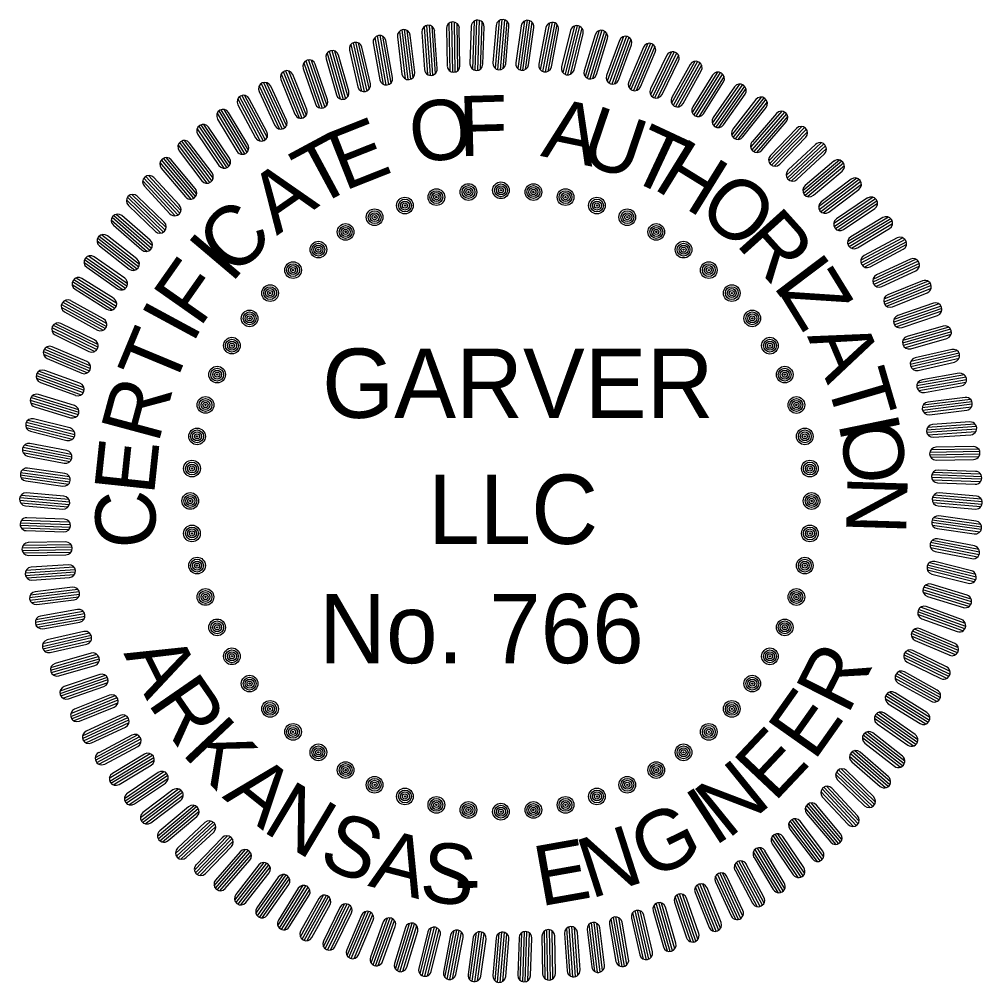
# Model space of a CAD drawing. Extents: x 1373862 to 1376999, y 1168398 to 1170455.
# Drawn here: x 1376477.4 to 1376713.7, y 1168432.6 to 1168668.8 of the extents above; entities that cross this region are included whole.
import ezdxf

# ---------------------------------------------------------------- set-up
doc = ezdxf.new("R2010")
doc.units = 0
doc.layers.add('G-ANNO-TEXT', color=7, linetype='Continuous')

# ---------------------------------------------------------------- blocks, each defined once
blk = doc.blocks.new('SEALDO')
at = {"layer": 'G-ANNO-TEXT'}
for radius in [0.0396, 0.0305, 0.0213, 0.0122, 0.00305]:
    blk.add_circle((1.403, -0.4559), radius, dxfattribs=at)
blk = doc.blocks.new('SEALRI')
at = {"layer": 'G-ANNO-TEXT'}
for p, q in [((-0.0226, 2.2583), (-0.0381, 2.0809)), ((-0.0083, 2.2815), (-0.0281, 2.0555)), ((0.0043, 2.2859), (-0.0164, 2.049)), ((0.0164, 2.2848), (-0.0043, 2.0479)), ((0.0281, 2.2783), (0.0083, 2.0523)), ((0.0226, 2.0756), (0.0381, 2.253))]:
    blk.add_line(p, q, dxfattribs=at)
for centre, start, end in [((0.0078, 2.2556), 355, 175), ((-0.0078, 2.0782), 175, 355)]:
    blk.add_arc(centre, 0.0305, start, end, dxfattribs=at)

msp = doc.modelspace()

# ---------------------------------------------------------------- block references
at = {"layer": 'G-ANNO-TEXT'}
for name, xscale, yscale, rotation in [('SEALRI', 51.64309671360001, 51.643096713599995, 3.0000000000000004), ('SEALRI', 51.64309671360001, 51.6430967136, -2.999999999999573), ('SEALRI', 51.643096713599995, 51.643096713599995, 12), ('SEALRI', 51.64309671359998, 51.64309671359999, 9.000000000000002), ('SEALRI', 51.6430967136, 51.643096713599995, 6.000000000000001), ('SEALRI', 51.6430967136, 51.643096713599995, -5.99999999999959), ('SEALRI', 51.643096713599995, 51.64309671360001, -8.999999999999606), ('SEALRI', 51.64309671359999, 51.64309671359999, -11.999999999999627), ('SEALRI', 51.643096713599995, 51.64309671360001, 15.000000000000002), ('SEALRI', 51.6430967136, 51.64309671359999, -14.99999999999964), ('SEALRI', 51.6430967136, 51.643096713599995, 20.99999999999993), ('SEALRI', 51.64309671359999, 51.64309671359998, 18.000000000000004), ('SEALRI', 51.643096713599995, 51.643096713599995, -17.999999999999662), ('SEALRI', 51.64309671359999, 51.64309671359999, -20.999999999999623), ('SEALRI', 51.6430967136, 51.643096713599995, 23.99999999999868), ('SEALRI', 51.643096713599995, 51.6430967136, -23.999999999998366), ('SEALRI', 51.6430967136, 51.643096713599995, 26.999999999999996), ('SEALRI', 51.643096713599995, 51.643096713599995, -26.99999999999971), ('SEALRI', 51.6430967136, 51.64309671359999, 30.000000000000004), ('SEALRI', 51.64309671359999, 51.6430967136, -29.999999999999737), ('SEALRI', 51.643096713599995, 51.64309671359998, 33), ('SEALRI', 51.6430967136, 51.6430967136, -32.999999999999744), ('SEALRI', 51.643096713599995, 51.64309671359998, 36), ('SEALRI', 51.643096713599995, 51.643096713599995, -35.999999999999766), ('SEALRI', 51.6430967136, 51.6430967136, 38.999999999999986), ('SEALRI', 51.64309671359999, 51.64309671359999, -38.99999999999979), ('SEALRI', 51.64309671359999, 51.64309671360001, 41.99999999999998), ('SEALRI', 51.6430967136, 51.643096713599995, -41.99999999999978), ('SEALRI', 51.643096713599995, 51.64309671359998, 44.999999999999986), ('SEALRI', 51.6430967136, 51.6430967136, -44.99999999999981), ('SEALRI', 51.643096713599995, 51.6430967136, 48), ('SEALRI', 51.6430967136, 51.643096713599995, -47.99999999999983), ('SEALDO', 51.64309671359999, 51.64309671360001, 113.99999999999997), ('SEALDO', 51.643096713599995, 51.64309671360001, 107.99999999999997), ('SEALDO', 51.64309671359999, 51.64309671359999, 101.99999999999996), ('SEALRI', 51.643096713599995, 51.6430967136, 50.99999999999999), ('SEALDO', 51.6430967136, 51.6430967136, 125.99999999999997), ('SEALDO', 51.64309671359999, 51.64309671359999, 119.99999999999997), ('SEALDO', 51.6430967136, 51.643096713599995, 95.99999999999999), ('SEALRI', 51.643096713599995, 51.6430967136, -50.99999999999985), ('SEALDO', 51.643096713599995, 51.643096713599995, 90), ('SEALRI', 51.643096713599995, 51.64309671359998, 54.00000000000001), ('SEALDO', 51.6430967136, 51.643096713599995, 131.99999999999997), ('SEALDO', 51.6430967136, 51.6430967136, 83.99999999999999), ('SEALRI', 51.6430967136, 51.643096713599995, -53.99999999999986), ('SEALDO', 51.643096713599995, 51.643096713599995, 138), ('SEALDO', 51.643096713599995, 51.6430967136, 77.99999999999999), ('SEALRI', 51.643096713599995, 51.6430967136, 56.999999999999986), ('SEALRI', 51.6430967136, 51.6430967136, -56.999999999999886), ('SEALDO', 51.64309671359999, 51.64309671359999, 144), ('SEALDO', 51.64309671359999, 51.64309671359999, 72), ('SEALRI', 51.64309671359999, 51.6430967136, 59.999999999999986), ('SEALDO', 51.643096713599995, 51.6430967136, 150), ('SEALDO', 51.6430967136, 51.6430967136, 66.00000000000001), ('SEALRI', 51.64309671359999, 51.64309671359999, -59.99999999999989), ('SEALRI', 51.64309671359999, 51.64309671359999, 63), ('SEALRI', 51.643096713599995, 51.6430967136, -62.99999999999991), ('SEALDO', 51.643096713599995, 51.6430967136, 156.00000000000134), ('SEALDO', 51.643096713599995, 51.6430967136, 60.00000000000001), ('SEALRI', 51.6430967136, 51.6430967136, 65.99999999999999), ('SEALRI', 51.6430967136, 51.64309671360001, -65.99999999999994), ('SEALDO', 51.64309671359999, 51.6430967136, 162.00000000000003), ('SEALDO', 51.643096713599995, 51.64309671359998, 54.00000000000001), ('SEALRI', 51.64309671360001, 51.6430967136, 68.99999999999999), ('SEALRI', 51.643096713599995, 51.6430967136, -68.99999999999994), ('SEALDO', 51.64309671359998, 51.643096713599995, 168.00000000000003), ('SEALDO', 51.6430967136, 51.643096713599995, 48.00000000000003), ('SEALRI', 51.64309671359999, 51.64309671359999, 72), ('SEALRI', 51.643096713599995, 51.6430967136, -71.99999999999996), ('SEALDO', 51.6430967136, 51.643096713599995, 174.00000000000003), ('SEALDO', 51.643096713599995, 51.6430967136, 42.00000000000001), ('SEALRI', 51.643096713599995, 51.6430967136, 75.00000000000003), ('SEALRI', 51.6430967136, 51.643096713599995, -74.99999999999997), ('SEALRI', 51.643096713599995, 51.643096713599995, 78.00000000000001), ('SEALDO', 51.643096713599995, 51.643096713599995, -179.99999999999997), ('SEALDO', 51.643096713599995, 51.64309671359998, 36), ('SEALRI', 51.643096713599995, 51.643096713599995, -78), ('SEALRI', 51.643096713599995, 51.64309671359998, 81), ('SEALDO', 51.643096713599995, 51.6430967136, 29.999999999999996), ('SEALRI', 51.64309671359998, 51.64309671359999, -81.00000000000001), ('SEALDO', 51.64309671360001, 51.643096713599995, -173.99999999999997), ('SEALRI', 51.6430967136, 51.643096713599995, 84.00000000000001), ('SEALRI', 51.6430967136, 51.643096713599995, -84.00000000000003), ('SEALDO', 51.64309671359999, 51.6430967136, -167.99999999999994), ('SEALDO', 51.6430967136, 51.643096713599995, 23.99999999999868), ('SEALRI', 51.6430967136, 51.6430967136, 87.00000000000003), ('SEALRI', 51.6430967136, 51.6430967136, -87.00000000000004), ('SEALRI', 51.643096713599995, 51.643096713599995, 90.00000000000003), ('SEALDO', 51.64309671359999, 51.64309671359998, -161.9999999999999), ('SEALDO', 51.64309671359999, 51.64309671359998, 18.000000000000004), ('SEALRI', 51.643096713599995, 51.643096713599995, -90.00000000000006), ('SEALRI', 51.64309671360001, 51.643096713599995, 93), ('SEALRI', 51.64309671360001, 51.6430967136, -93.00000000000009), ('SEALDO', 51.6430967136, 51.6430967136, -156.00000000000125), ('SEALDO', 51.643096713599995, 51.643096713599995, 12), ('SEALRI', 51.6430967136, 51.6430967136, 96.00000000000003), ('SEALRI', 51.643096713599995, 51.643096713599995, -96.0000000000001), ('SEALRI', 51.643096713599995, 51.643096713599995, 99.00000000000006), ('SEALDO', 51.6430967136, 51.643096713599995, -149.99999999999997), ('SEALDO', 51.6430967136, 51.643096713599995, 6.000000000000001), ('SEALRI', 51.643096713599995, 51.643096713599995, -99.00000000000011), ('SEALRI', 51.64309671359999, 51.64309671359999, 102.00000000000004), ('SEALDO', 51.64309671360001, 51.6430967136, -143.99999999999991), ('SEALRI', 51.643096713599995, 51.6430967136, -102.00000000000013), ('SEALRI', 51.6430967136, 51.643096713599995, 105.00000000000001), ('SEALRI', 51.6430967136, 51.643096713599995, -105.00000000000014), ('SEALDO', 51.6430967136, 51.6430967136, -137.9999999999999), ('SEALDO', 51.6430967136, 51.6430967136, -6.000000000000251), ('SEALRI', 51.643096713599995, 51.6430967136, 108.00000000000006), ('SEALRI', 51.6430967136, 51.643096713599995, -108.00000000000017), ('SEALDO', 51.643096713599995, 51.643096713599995, -131.99999999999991), ('SEALDO', 51.64309671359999, 51.64309671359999, -12.000000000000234), ('SEALRI', 51.64309671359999, 51.6430967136, 111.00000000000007), ('SEALRI', 51.643096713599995, 51.643096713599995, -111.00000000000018), ('SEALRI', 51.6430967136, 51.643096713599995, 114.00000000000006), ('SEALDO', 51.6430967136, 51.643096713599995, -125.9999999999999), ('SEALDO', 51.64309671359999, 51.64309671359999, -18.00000000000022), ('SEALRI', 51.6430967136, 51.643096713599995, -114.0000000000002), ('SEALRI', 51.64309671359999, 51.64309671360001, 117.00000000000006), ('SEALRI', 51.64309671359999, 51.643096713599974, -117.00000000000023), ('SEALDO', 51.64309671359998, 51.643096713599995, -119.99999999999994), ('SEALDO', 51.643096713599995, 51.64309671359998, -23.999999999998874), ('SEALRI', 51.64309671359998, 51.643096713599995, 120.00000000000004), ('SEALRI', 51.643096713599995, 51.6430967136, -120.00000000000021), ('SEALDO', 51.643096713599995, 51.64309671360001, -113.99999999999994), ('SEALDO', 51.64309671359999, 51.64309671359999, -30.00000000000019), ('SEALRI', 51.64309671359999, 51.6430967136, 123.00000000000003), ('SEALRI', 51.643096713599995, 51.6430967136, -123.00000000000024), ('SEALDO', 51.643096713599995, 51.6430967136, -107.99999999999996), ('SEALDO', 51.643096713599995, 51.643096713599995, -36.00000000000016), ('SEALRI', 51.643096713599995, 51.6430967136, 126.00000000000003), ('SEALRI', 51.643096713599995, 51.643096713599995, -126.00000000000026), ('SEALDO', 51.643096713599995, 51.64309671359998, -101.99999999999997), ('SEALDO', 51.643096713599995, 51.643096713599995, -42.00000000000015), ('SEALRI', 51.643096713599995, 51.6430967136, 129.00000000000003), ('SEALRI', 51.64309671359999, 51.64309671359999, -129.00000000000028), ('SEALDO', 51.6430967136, 51.643096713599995, -96), ('SEALDO', 51.6430967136, 51.64309671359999, -48.00000000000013), ('SEALRI', 51.643096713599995, 51.643096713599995, 132), ('SEALDO', 51.643096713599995, 51.643096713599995, -90.00000000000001), ('SEALDO', 51.643096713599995, 51.64309671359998, -54.00000000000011), ('SEALRI', 51.64309671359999, 51.64309671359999, -132.00000000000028), ('SEALRI', 51.64309671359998, 51.64309671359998, 135), ('SEALDO', 51.6430967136, 51.643096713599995, -84.00000000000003), ('SEALDO', 51.64309671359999, 51.64309671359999, -78.00000000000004), ('SEALDO', 51.643096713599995, 51.643096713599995, -72.00000000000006), ('SEALDO', 51.643096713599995, 51.643096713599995, -66.00000000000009), ('SEALDO', 51.643096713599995, 51.6430967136, -60.0000000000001), ('SEALRI', 51.643096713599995, 51.643096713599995, -135.00000000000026), ('SEALRI', 51.643096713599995, 51.643096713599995, 138), ('SEALRI', 51.643096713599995, 51.64309671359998, -138.00000000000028), ('SEALRI', 51.643096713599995, 51.643096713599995, 140.99999999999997), ('SEALRI', 51.64309671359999, 51.64309671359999, -141.0000000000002), ('SEALRI', 51.64309671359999, 51.64309671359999, 144), ('SEALRI', 51.643096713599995, 51.643096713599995, -144.00000000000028), ('SEALRI', 51.6430967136, 51.643096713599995, 146.99999999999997), ('SEALRI', 51.6430967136, 51.6430967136, -147.00000000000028), ('SEALRI', 51.643096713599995, 51.6430967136, 149.99999999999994), ('SEALRI', 51.6430967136, 51.643096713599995, -150.00000000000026), ('SEALRI', 51.6430967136, 51.643096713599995, 152.99999999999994), ('SEALRI', 51.64309671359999, 51.6430967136, -153.00000000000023), ('SEALRI', 51.6430967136, 51.64309671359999, 156.00000000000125), ('SEALRI', 51.6430967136, 51.6430967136, -156.00000000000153), ('SEALRI', 51.643096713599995, 51.6430967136, 159), ('SEALRI', 51.643096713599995, 51.6430967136, -159.00000000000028), ('SEALRI', 51.64309671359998, 51.64309671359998, 161.99999999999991), ('SEALRI', 51.64309671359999, 51.64309671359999, 164.99999999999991), ('SEALRI', 51.643096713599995, 51.64309671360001, -165.0000000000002), ('SEALRI', 51.64309671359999, 51.64309671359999, -162.00000000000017), ('SEALRI', 51.643096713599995, 51.64309671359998, 167.99999999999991), ('SEALRI', 51.643096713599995, 51.643096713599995, 170.9999999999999), ('SEALRI', 51.643096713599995, 51.6430967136, -171.00000000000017), ('SEALRI', 51.643096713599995, 51.6430967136, -168.0000000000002), ('SEALRI', 51.643096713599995, 51.6430967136, 173.9999999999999), ('SEALRI', 51.64309671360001, 51.6430967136, 176.9999999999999), ('SEALRI', 51.643096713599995, 51.643096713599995, 179.99999999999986), ('SEALRI', 51.64309671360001, 51.6430967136, -177.00000000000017), ('SEALRI', 51.643096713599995, 51.643096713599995, -174.00000000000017)]:
    msp.add_blockref(name, (1376595.54, 1168550.72), dxfattribs=dict(at, xscale=xscale, yscale=yscale, rotation=rotation))
at = {"layer": 'G-ANNO-TEXT', "xscale": 51.643096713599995, "yscale": 51.643096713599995}
for name in ['SEALRI', 'SEALDO']:
    msp.add_blockref(name, (1376595.54, 1168550.72), dxfattribs=at)

# ---------------------------------------------------------------- texts
at = {"layer": 'G-ANNO-TEXT'}
for s, rotation, p in [('O', 8.2771, (1376574.16, 1168633.31)), ('F', 1.6104, (1376585.35, 1168635.23)), ('A', 348.2771, (1376605.07, 1168635.36)), ('U', 341.2772, (1376614.3, 1168633.88)), ('E', 21.6104, (1376557.07, 1168626.66)), ('T', 334.9438, (1376625.9, 1168630.14)), ('T', 28.2771, (1376549.94, 1168622.49)), ('H', 328.2771, (1376632.54, 1168627.52)), ('A', 34.9438, (1376540.55, 1168615.7)), ('O', 319.7874, (1376643.21, 1168621.46)), ('C', 44.3881, (1376530.1, 1168605.3)), ('R', 311.9933, (1376652.89, 1168613.73)), ('I', 49.7408, (1376529.34, 1168603.79)), ('F', 54.9438, (1376521.66, 1168592.98)), ('I', 307.0081, (1376661.9, 1168603.61)), ('Z', 301.6104, (1376663.64, 1168601.83)), ('I', 61.6104, (1376519.9, 1168589)), ('T', 67.4314, (1376514.94, 1168577.56)), ('A', 292.9752, (1376670.59, 1168591.12)), ('T', 286.3085, (1376675.21, 1168580.43)), ('R', 74.9438, (1376511.49, 1168564.56)), ('I', 281.6104, (1376678.17, 1168570.05)), ('O', 276.4823, (1376678.74, 1168569.52)), ('E', 83.8985, (1376510.43, 1168551.94)), ('N', 268.2771, (1376680.58, 1168557.07)), ('C', 91.8842, (1376511.08, 1168539.35)), ('A', 296.5747, (1376502.89, 1168513.34)), ('R', 63.0959, (1376680.56, 1168498.02)), ('R', 304.6183, (1376508.71, 1168501.19)), ('E', 54.7309, (1376672.35, 1168486.7)), ('K', 313.3805, (1376517, 1168488.84)), ('E', 46.6807, (1376662.58, 1168476.62)), ('N', 38.9821, (1376651.17, 1168467.6)), ('A', 321.2584, (1376526.98, 1168478.05)), ('N', 329.1099, (1376536.68, 1168469.89)), ('I', 32.979, (1376647.75, 1168465.85)), ('G', 26.4132, (1376632.09, 1168457.62)), ('S', 337.6294, (1376550.3, 1168461.59)), ('N', 17.8686, (1376617.55, 1168453.11)), ('A', 345.4073, (1376562.72, 1168456.37)), ('E', 10.0695, (1376605.2, 1168451.28)), ('S', 352.8046, (1376575.24, 1168452.86)), ('-', 0.8385, (1376584.15, 1168450.93))]:
    msp.add_text(s, height=14.76, rotation=rotation, dxfattribs=at).set_placement(p)
for s, p in [('GARVER', (1376551.68, 1168571.1)), ('LLC', (1376577.67, 1168540.19)), ('No. 766', (1376550.94, 1168510.94))]:
    msp.add_text(s, height=17, dxfattribs=at).set_placement(p)

doc.saveas('drawing.dxf')
